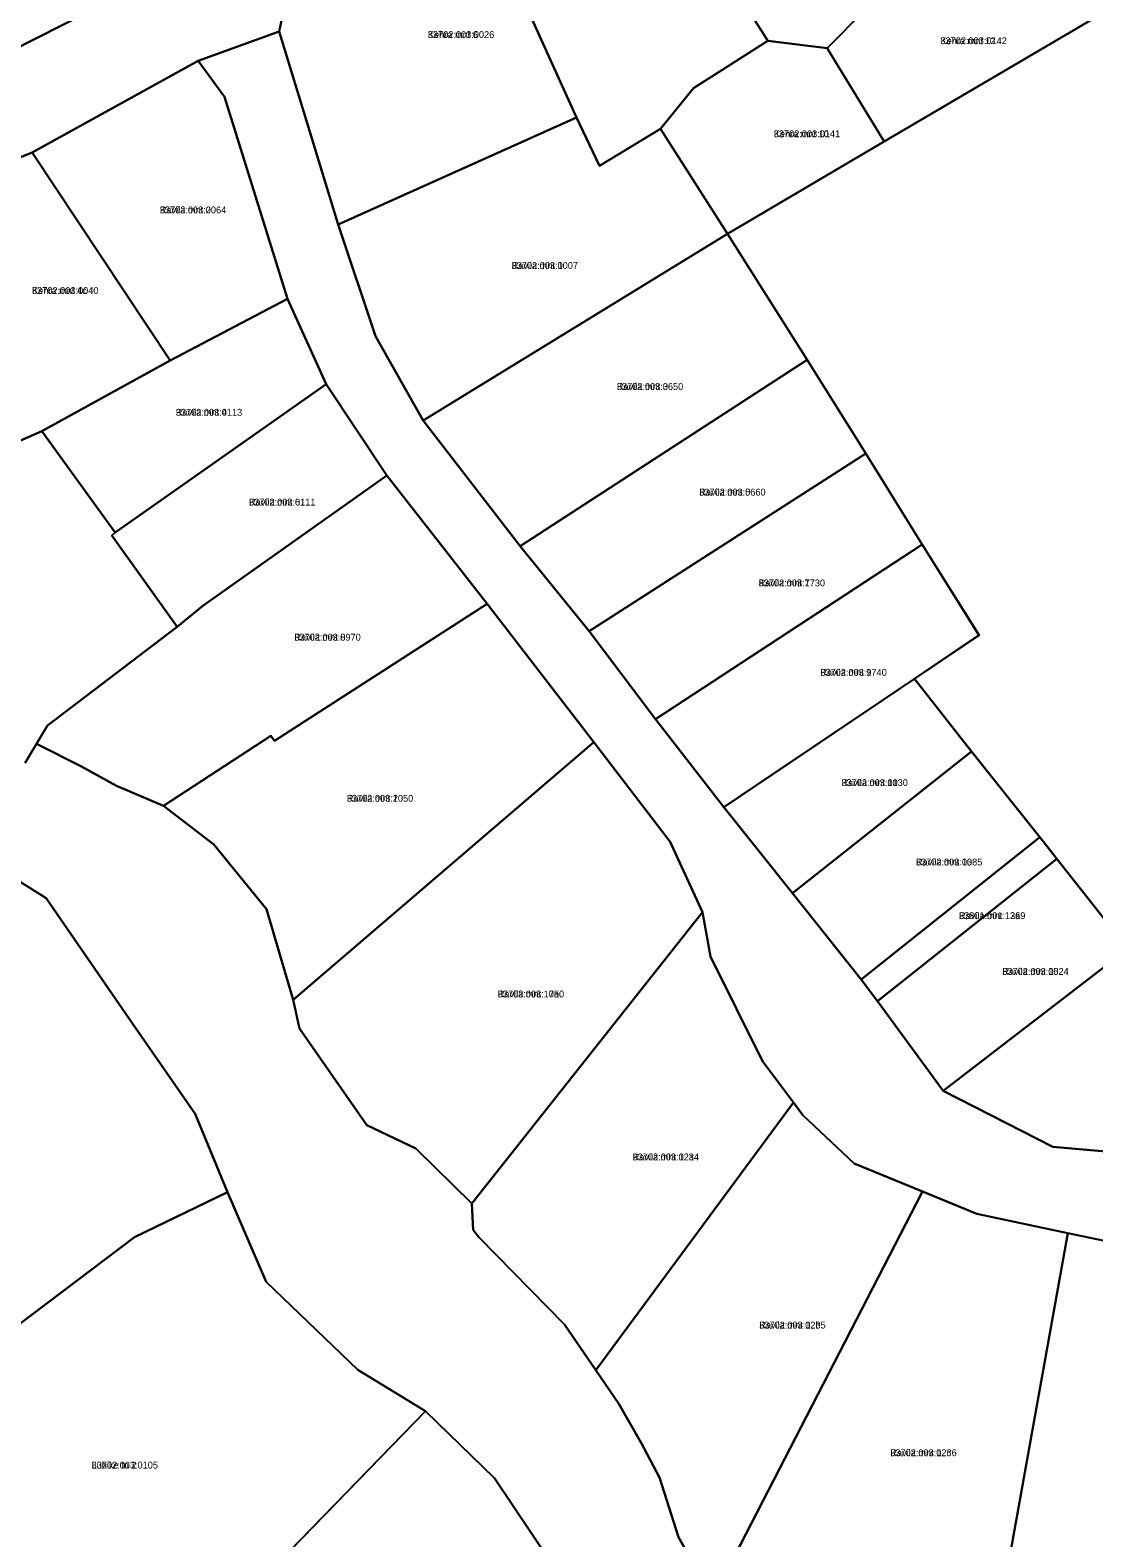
# Model space of a CAD drawing. Extents: x 551583 to 585220, y 6539942 to 6568852.
# Drawn here: x 566814.5 to 567046.8, y 6561149.5 to 6561478.7 of the extents above; entities that cross this region are included whole.
import ezdxf

# ---------------------------------------------------------------- set-up
doc = ezdxf.new("R2010")
doc.units = 0
for name, color, linetype in [('L_AADRESS', 7, 'Continuous'), ('PIIR', 7, 'Continuous'), ('TUNNUS', 7, 'Continuous')]:
    doc.layers.add(name, color=color, linetype=linetype)

msp = doc.modelspace()

# ---------------------------------------------------------------- linework, layer by layer
at = {"layer": 'PIIR'}
for points in [[(566791.18, 6561508.65), (566842.94, 6561542.25), (566867.01, 6561508.04), (566866.2, 6561503.29), (566839.93, 6561486.97), (566838.87, 6561488.68), (566809.96, 6561473.95)], [(566948.67, 6561539.87), (566956.37, 6561544.97), (566973.41, 6561513.73), (566980.9, 6561500), (566984.74, 6561502.36), (566985.66, 6561500.92), (566996.96, 6561483.24), (566988.51, 6561474.77), (566975.56, 6561476.38), (566970.22, 6561484.87), (566971.82, 6561497.43), (566965.07, 6561509.81)], [(566906.76, 6561512.12), (566915.78, 6561499.26), (566922.92, 6561483.55), (566933.79, 6561459.63), (566881.75, 6561436.28), (566868.9, 6561478.35), (566871.51, 6561490.84)], [(566922.92, 6561483.55), (566965.07, 6561509.81), (566971.82, 6561497.43), (566970.22, 6561484.87), (566975.56, 6561476.38), (566959.32, 6561466), (566952.12, 6561457.15), (566938.8, 6561449.05), (566933.79, 6561459.63)], [(566996.96, 6561483.24), (567044.1, 6561496.48), (567045.47, 6561496.87), (567053.18, 6561485.02), (567001.02, 6561454.38), (566988.51, 6561474.77)], [(566952.12, 6561457.15), (566959.32, 6561466), (566975.56, 6561476.38), (566988.51, 6561474.77), (567001.02, 6561454.38), (566966.77, 6561434.22)], [(566856.96, 6561464.11), (566870.69, 6561420), (566845.09, 6561406.59), (566814.94, 6561452), (566851.2, 6561471.97)], [(566938.8, 6561449.05), (566952.12, 6561457.15), (566966.77, 6561434.22), (566900.3, 6561393.47), (566889.91, 6561411.89), (566881.75, 6561436.28), (566933.79, 6561459.63)], [(566784.73, 6561439.81), (566814.94, 6561452), (566845.09, 6561406.59), (566817.08, 6561391.11), (566812.26, 6561389.03), (566790.24, 6561429.29)], [(566900.3, 6561393.47), (566966.77, 6561434.22), (566984.2, 6561406.7), (566921.47, 6561366.04)], [(566817.08, 6561391.11), (566845.09, 6561406.59), (566870.69, 6561420), (566879.15, 6561401.36), (566833.09, 6561369)], [(566997, 6561386.24), (566936.56, 6561347.44), (566921.47, 6561366.04), (566984.2, 6561406.7)], [(566879.15, 6561401.36), (566892.35, 6561381.45), (566852.19, 6561353.01), (566846.6, 6561348.44), (566832.37, 6561368.36), (566833.09, 6561369)], [(566997, 6561386.24), (567009.3, 6561366.42), (566951.06, 6561328.26), (566936.56, 6561347.44)], [(566833.35, 6561313.73), (566825.54, 6561318.01), (566815.92, 6561322.84), (566818.32, 6561326.88), (566846.6, 6561348.44), (566852.19, 6561353.01), (566892.35, 6561381.45), (566914.28, 6561353.46), (566867.85, 6561323.55), (566867.08, 6561324.63), (566843.61, 6561309.35)], [(567009.3, 6561366.42), (567021.7, 6561346.56), (566966, 6561309.04), (566951.06, 6561328.26)], [(566866.13, 6561286.76), (566854.59, 6561300.88), (566843.61, 6561309.35), (566867.08, 6561324.63), (566867.85, 6561323.55), (566914.28, 6561353.46), (566937.56, 6561323.27), (566871.91, 6561267)], [(567007.6, 6561337.04), (567020.03, 6561321.21), (566980.95, 6561290.25), (566966, 6561309.04)], [(566898.75, 6561234.53), (566888.04, 6561239.62), (566873.32, 6561260.7), (566871.91, 6561267), (566937.56, 6561323.27), (566954.27, 6561301.51), (566961.3, 6561286.13), (566910.94, 6561222.55)], [(566995.95, 6561271.42), (566980.95, 6561290.25), (567020.03, 6561321.21), (567035.01, 6561302.5)], [(567038.7, 6561297.75), (566999.55, 6561266.72), (566995.95, 6561271.42), (567035.01, 6561302.5)], [(567054.16, 6561278.11), (567013.85, 6561247.13), (566999.55, 6561266.72), (567038.71, 6561297.75)], [(566773.29, 6561214.3), (566745.37, 6561201.46), (566734.14, 6561227.25), (566809.58, 6561294.52), (566817.97, 6561289.18), (566836.97, 6561261.57), (566850.55, 6561242.08), (566857.57, 6561225.02), (566837.25, 6561215.15), (566795.8, 6561183.85)], [(566961.3, 6561286.13), (566963.06, 6561276.42), (566974.42, 6561253.63), (566981.16, 6561244.54), (566938.03, 6561186.13), (566931.16, 6561196.13), (566912.45, 6561215.19), (566911.21, 6561216.76), (566910.94, 6561222.55)], [(567037.85, 6561234.91), (567013.85, 6561247.13), (567054.16, 6561278.11), (567086.48, 6561273.07), (567056.78, 6561233.25)], [(566981.16, 6561244.54), (566983.22, 6561241.78), (566994.43, 6561231.25), (567009.38, 6561225.11), (566963.56, 6561136.37), (566956.07, 6561149.67), (566951.91, 6561162.69), (566947.93, 6561170.28), (566943.01, 6561178.77), (566938.03, 6561186.13)], [(566754.97, 6561156.5), (566795.8, 6561183.85), (566837.25, 6561215.15), (566857.57, 6561225.02), (566866.03, 6561205.42), (566886.02, 6561186.2), (566900.8, 6561177.15), (566829.99, 6561104.3), (566800.56, 6561133.37), (566785.57, 6561147.3), (566753.17, 6561139.22)], [(567009.38, 6561225.11), (567021.2, 6561220.25), (567041.08, 6561216.05), (567024.89, 6561125.77), (567011.42, 6561122.99), (566997.55, 6561123.43), (566991.63, 6561123.93), (566982.74, 6561125.46), (566978.35, 6561127.07), (566975.21, 6561128.66), (566967.77, 6561132.95), (566963.56, 6561136.37)], [(567041.08, 6561216.05), (567050.84, 6561213.98), (567059.56, 6561214.54), (567094.82, 6561213.86), (567117.7, 6561216.2), (567137.16, 6561219.41), (567139.86, 6561162.66), (567137.23, 6561159.9), (567130.08, 6561155.24), (567121.24, 6561151.93), (567117.85, 6561149.93), (567110.9, 6561146.82), (567090.24, 6561138.14), (567081.01, 6561137.47), (567072.61, 6561135.39), (567063.9, 6561133.31), (567056.02, 6561132.9), (567034.1, 6561127.5), (567024.89, 6561125.77)], [(566900.8, 6561177.15), (566915.9, 6561162.59), (566927.91, 6561144.68), (566856, 6561098.06), (566838.72, 6561113.28)]]:
    msp.add_lwpolyline(points, close=True, dxfattribs=at)
for points in [[(566871.51, 6561490.84), (566868.9, 6561478.35), (566851.2, 6561471.97), (566814.94, 6561452), (566784.73, 6561439.81), (566780.27, 6561448.19), (566761.37, 6561448.1), (566710.22, 6561455.27), (566678.07, 6561461.27), (566660.57, 6561464.53), (566651.97, 6561466.15), (566644.26, 6561466.97), (566579.42, 6561476.07), (566505.33, 6561488.91)], [(566741.82, 6561481.07), (566781.7, 6561465.52), (566809.96, 6561473.95), (566838.87, 6561488.68)], [(567351.9, 6561344.3), (567318.05, 6561329.25), (567314.79, 6561333.27), (567300.12, 6561354.75), (567277.32, 6561387.96), (567235.86, 6561360.17), (567229.77, 6561356.06), (567189.18, 6561328.83), (567142.47, 6561297.47), (567102.42, 6561270.59), (567086.48, 6561273.07), (567054.16, 6561278.11), (567038.7, 6561297.75), (567035.01, 6561302.49), (567020.04, 6561321.21), (567007.59, 6561337.04), (567021.69, 6561346.56), (567009.3, 6561366.42), (566997, 6561386.24), (566984.19, 6561406.71), (566966.76, 6561434.22), (567001.02, 6561454.38), (567053.19, 6561485.03)], [(567050.84, 6561213.98), (567041.08, 6561216.05), (567021.2, 6561220.25), (567009.38, 6561225.11), (566994.43, 6561231.25), (566983.22, 6561241.78), (566981.16, 6561244.54), (566974.42, 6561253.63), (566963.06, 6561276.42), (566961.3, 6561286.13), (566954.27, 6561301.51), (566937.56, 6561323.27), (566914.28, 6561353.46), (566892.35, 6561381.45), (566879.15, 6561401.36), (566870.69, 6561420), (566856.96, 6561464.11), (566851.2, 6561471.97), (566868.9, 6561478.35), (566881.75, 6561436.28), (566889.91, 6561411.89), (566900.3, 6561393.47), (566921.47, 6561366.04), (566936.56, 6561347.44), (566951.06, 6561328.26), (566966, 6561309.04), (566980.95, 6561290.25), (566995.95, 6561271.42), (566999.55, 6561266.72), (567013.85, 6561247.13), (567037.85, 6561234.91), (567056.78, 6561233.25)], [(566812.26, 6561389.03), (566817.08, 6561391.11), (566833.09, 6561369), (566832.37, 6561368.36), (566846.6, 6561348.44), (566818.32, 6561326.88), (566815.92, 6561322.84), (566813.42, 6561318.76)], [(566813.42, 6561318.76), (566815.92, 6561322.84), (566825.54, 6561318.01), (566833.35, 6561313.73), (566843.61, 6561309.35), (566854.59, 6561300.88), (566866.13, 6561286.76), (566871.91, 6561267), (566873.32, 6561260.7), (566888.04, 6561239.62), (566898.75, 6561234.53), (566910.94, 6561222.55), (566911.21, 6561216.76), (566912.45, 6561215.19), (566931.16, 6561196.13), (566938.03, 6561186.13), (566943.01, 6561178.77), (566947.93, 6561170.28), (566951.91, 6561162.69), (566956.07, 6561149.67), (566963.56, 6561136.37)], [(566927.91, 6561144.68), (566915.9, 6561162.59), (566900.8, 6561177.15), (566886.02, 6561186.2), (566866.03, 6561205.42), (566857.57, 6561225.02), (566850.55, 6561242.08), (566836.97, 6561261.57), (566817.97, 6561289.18), (566809.58, 6561294.52)]]:
    msp.add_lwpolyline(points, dxfattribs=at)

# ---------------------------------------------------------------- texts
at = {"layer": 'L_AADRESS'}
for s, p in [('Kehra mnt 6', (566901.34, 6561476.96)), ('Kehra mnt 12', (567013.27, 6561475.62)), ('Kehra mnt 10', (566976.88, 6561455.3)), ('Ravila mnt 2', (566842.81, 6561438.68)), ('Ravila mnt 1', (566919.63, 6561426.55)), ('Kehra mnt 4c', (566814.91, 6561421.08)), ('Ravila mnt 3', (566942.61, 6561400.13)), ('Ravila mnt 4', (566846.3, 6561394.5)), ('Ravila mnt 5', (566960.6, 6561377.07)), ('Ravila mnt 6', (566862.29, 6561374.9)), ('Ravila mnt 7', (566973.57, 6561357.25)), ('Ravila mnt 8', (566872.19, 6561345.4)), ('Ravila mnt 9', (566987.05, 6561337.73)), ('Ravila mnt 11', (566991.66, 6561313.65)), ('Ravila mnt 10', (566883.65, 6561310.23)), ('Ravila mnt 13', (567007.92, 6561296.32)), ('Ravila mnt 13a', (567017.32, 6561284.61)), ('Ravila mnt 15', (567026.78, 6561272.44)), ('Ravila mnt 10a', (566916.6, 6561267.51)), ('Ravila mnt 12a', (566946.05, 6561231.93)), ('Ravila mnt 12b', (566973.71, 6561195.23)), ('Ravila mnt 12c', (567002.32, 6561167.36)), ('Lühike tn 2', (566827.91, 6561164.66))]:
    msp.add_text(s, height=1.5, dxfattribs=at).set_placement(p)
at = {"layer": 'TUNNUS'}
for s, p in [('33702:003:0026', (566901.34, 6561476.96)), ('33702:003:0142', (567013.27, 6561475.62)), ('33702:003:0141', (566976.88, 6561455.3)), ('33702:003:0064', (566842.81, 6561438.68)), ('33702:003:0007', (566919.63, 6561426.55)), ('33702:003:0040', (566814.91, 6561421.08)), ('33702:003:0650', (566942.61, 6561400.13)), ('33702:003:0113', (566846.3, 6561394.5)), ('33702:003:0660', (566960.6, 6561377.07)), ('33702:003:0111', (566862.29, 6561374.9)), ('33702:003:1730', (566973.57, 6561357.25)), ('33702:003:0970', (566872.19, 6561345.4)), ('33702:003:1740', (566987.05, 6561337.73)), ('33702:003:0030', (566991.66, 6561313.65)), ('33702:003:2050', (566883.65, 6561310.23)), ('33702:003:0085', (567007.92, 6561296.32)), ('33801:001:1269', (567017.32, 6561284.61)), ('33702:003:0024', (567026.78, 6561272.44)), ('33702:003:1750', (566916.6, 6561267.51)), ('33702:003:0234', (566946.05, 6561231.93)), ('33702:003:0235', (566973.71, 6561195.23)), ('33702:003:0236', (567002.32, 6561167.36)), ('33702:003:0105', (566827.91, 6561164.66))]:
    msp.add_text(s, height=1.5, dxfattribs=at).set_placement(p)

doc.saveas('drawing.dxf')
